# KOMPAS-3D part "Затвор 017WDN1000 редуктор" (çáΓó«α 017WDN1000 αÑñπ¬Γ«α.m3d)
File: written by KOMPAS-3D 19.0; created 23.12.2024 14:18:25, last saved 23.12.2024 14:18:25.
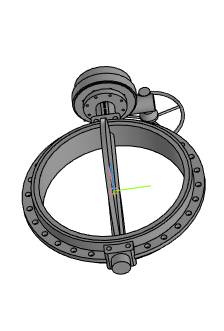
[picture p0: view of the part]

Document properties: Автор: Евгений; Полное имя файла: ..\Затвор 017WDN1000 редуктор.a3d

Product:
- Part/product: Затвор 017WDN1000 редуктор
    Масса: 893.804

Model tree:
1. Операция без истории:1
